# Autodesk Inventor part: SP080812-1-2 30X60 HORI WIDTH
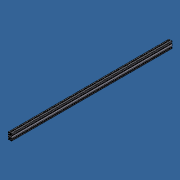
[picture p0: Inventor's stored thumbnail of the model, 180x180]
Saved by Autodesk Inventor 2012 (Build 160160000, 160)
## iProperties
Created: 2012-08
Part Number: SP080812-1-2 30X60 HORI WIDTH
Material: Aluminum-6061
Description: PROFILE 30X60
Document SubType Name: Modeling
Designer: Administrator
Stock Number: 20.0994 PROFILE 30X60
Density: 2.71 g/cm^3
Author: Administrator
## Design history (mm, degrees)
sketch "Sketch1"
  geometry: L1 (-12.5, -19.1)-(-12.5, -21.8); L2 (-15, -19.1)-(-12.5, -19.1); L3 (-15, -30)-(-15, -19.1); L4 (-4.1, -30)-(-15, -30); L5 (-4.1, -27.5)-(-4.1, -30); L6 (-6.8, -27.5)-(-4.1, -27.5); L7 (-6.8, -22.861)-(-6.8, -27.5); L8 (-3.939, -20)-(-6.8, -22.861); L9 (3.939, -20)-(-3.939, -20); L10 (6.8, -22.861)-(3.939, -20); L11 (6.8, -27.5)-(6.8, -22.861); L12 (4.1, -27.5)-(6.8, -27.5); L13 (4.1, -30)-(4.1, -27.5); L14 (15, -30)-(4.1, -30); L15 (15, -19.1)-(15, -30); L16 (12.5, -19.1)-(15, -19.1); L17 (12.5, -21.8)-(12.5, -19.1); L18 (7.861, -21.8)-(12.5, -21.8); L19 (5, -18.939)-(7.861, -21.8); L20 (5, -11.061)-(5, -18.939); L21 (7.861, -8.2)-(5, -11.061); L22 (12.5, -8.2)-(7.861, -8.2); L23 (12.5, -10.9)-(12.5, -8.2); L24 (15, -10.9)-(12.5, -10.9); L25 (15, 10.9)-(15, -10.9); L26 (12.5, 10.9)-(15, 10.9); L27 (12.5, 8.2)-(12.5, 10.9); L28 (7.861, 8.2)-(12.5, 8.2); L29 (5, 11.061)-(7.861, 8.2); L30 (5, 18.939)-(5, 11.061); L31 (7.861, 21.8)-(5, 18.939); L32 (12.5, 21.8)-(7.861, 21.8); L33 (12.5, 19.1)-(12.5, 21.8); L34 (15, 19.1)-(12.5, 19.1); L35 (15, 30)-(15, 19.1); L36 (4.1, 30)-(15, 30); L37 (4.1, 27.5)-(4.1, 30); L38 (6.8, 27.5)-(4.1, 27.5); L39 (6.8, 22.861)-(6.8, 27.5); L40 (3.939, 20)-(6.8, 22.861); L41 (-3.939, 20)-(3.939, 20); L42 (-6.8, 22.861)-(-3.939, 20); L43 (-6.8, 27.5)-(-6.8, 22.861); L44 (-4.1, 27.5)-(-6.8, 27.5); L45 (-4.1, 30)-(-4.1, 27.5); L46 (-15, 30)-(-4.1, 30); L47 (-15, 19.1)-(-15, 30); L48 (-12.5, 19.1)-(-15, 19.1); L49 (-12.5, 21.8)-(-12.5, 19.1); L50 (-7.861, 21.8)-(-12.5, 21.8); L51 (-5, 18.939)-(-7.861, 21.8); L52 (-5, 11.061)-(-5, 18.939); L53 (-7.861, 8.2)-(-5, 11.061); L54 (-12.5, 8.2)-(-7.861, 8.2); L55 (-12.5, 10.9)-(-12.5, 8.2); L56 (-15, 10.9)-(-12.5, 10.9); L57 (-15, -10.9)-(-15, 10.9); L58 (-12.5, -10.9)-(-15, -10.9); L59 (-12.5, -8.2)-(-12.5, -10.9); L60 (-7.861, -8.2)-(-12.5, -8.2); L61 (-5, -11.061)-(-7.861, -8.2); L62 (-5, -18.939)-(-5, -11.061); L63 (-7.861, -21.8)-(-5, -18.939); L64 (-12.5, -21.8)-(-7.861, -21.8)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; A1 r 0.5 centre (13.5, -23.3) between (14, -23.3) and (13.5, -22.8); A2 r 1.5 centre (12.5, -27.5) between (12.5, -29) and (14, -27.5); A3 r 0.5 centre (8.3, -28.5) between (7.8, -28.5) and (8.3, -29); A4 r 1.5 centre (9.3, -24.3) between (9.3, -22.8) and (7.8, -24.3); A5 r 0.5 centre (-8.3, -28.5) between (-8.3, -29) and (-7.8, -28.5); A6 r 1.5 centre (-12.5, -27.5) between (-14, -27.5) and (-12.5, -29); A7 r 0.5 centre (-13.5, -23.3) between (-13.5, -22.8) and (-14, -23.3); A8 r 1.5 centre (-9.3, -24.3) between (-7.8, -24.3) and (-9.3, -22.8); A9 r 0.3 centre (-1.793, -11.369) between (-2.005, -11.581) and (-1.66, -11.638); A10 r 3.75 centre (0, -15) between (1.66, -11.638) and (-1.66, -11.638); A11 r 0.3 centre (1.793, -11.369) between (1.66, -11.638) and (2.005, -11.581); A12 r 0.5 centre (3, -12) between (3.5, -12) and (3, -11.5); A13 r 0.3 centre (3.631, -13.207) between (3.419, -12.995) and (3.362, -13.34); A14 r 3.75 centre (0, -15) between (3.362, -16.66) and (3.362, -13.34); A15 r 0.3 centre (3.631, -16.793) between (3.362, -16.66) and (3.419, -17.005); A16 r 0.5 centre (3, -18) between (3, -18.5) and (3.5, -18); A17 r 0.3 centre (1.793, -18.631) between (2.005, -18.419) and (1.66, -18.362); A18 r 3.75 centre (0, -15) between (-1.66, -18.362) and (1.66, -18.362); A19 r 0.3 centre (-1.793, -18.631) between (-1.66, -18.362) and (-2.005, -18.419); A20 r 0.5 centre (-3, -18) between (-3.5, -18) and (-3, -18.5); A21 r 0.3 centre (-3.631, -16.793) between (-3.419, -17.005) and (-3.362, -16.66); A22 r 3.75 centre (0, -15) between (-3.362, -13.34) and (-3.362, -16.66); A23 r 0.3 centre (-3.631, -13.207) between (-3.362, -13.34) and (-3.419, -12.995); A24 r 0.5 centre (-3, -12) between (-3, -11.5) and (-3.5, -12); A25 r 0.5 centre (13.5, 6.7) between (14, 6.7) and (13.5, 7.2); A26 r 0.5 centre (13.5, -6.7) between (13.5, -7.2) and (14, -6.7); A27 r 1 centre (7.154, -8.2) between (7.154, -7.2) and (6.446, -7.493); A28 r 1 centre (3.525, -9) between (3.525, -10) and (4.232, -9.707); A29 r 1 centre (-3.525, -9) between (-4.232, -9.707) and (-3.525, -10); A30 r 1 centre (-7.154, -8.2) between (-6.446, -7.493) and (-7.154, -7.2); A31 r 0.5 centre (-13.5, -6.7) between (-14, -6.7) and (-13.5, -7.2); A32 r 0.5 centre (-13.5, 6.7) between (-13.5, 7.2) and (-14, 6.7); A33 r 1 centre (-7.154, 8.2) between (-7.154, 7.2) and (-6.446, 7.493); A34 r 1 centre (-3.525, 9) between (-3.525, 10) and (-4.232, 9.707); A35 r 1 centre (3.525, 9) between (4.232, 9.707) and (3.525, 10); A36 r 1 centre (7.154, 8.2) between (6.446, 7.493) and (7.154, 7.2); A37 r 0.3 centre (3.631, 16.793) between (3.419, 17.005) and (3.362, 16.66); A38 r 3.75 centre (0, 15) between (3.362, 13.34) and (3.362, 16.66); A39 r 0.3 centre (3.631, 13.207) between (3.362, 13.34) and (3.419, 12.995); A40 r 0.5 centre (3, 12) between (3, 11.5) and (3.5, 12); A41 r 0.3 centre (1.793, 11.369) between (2.005, 11.581) and (1.66, 11.638); A42 r 3.75 centre (0, 15) between (-1.66, 11.638) and (1.66, 11.638); A43 r 0.3 centre (-1.793, 11.369) between (-1.66, 11.638) and (-2.005, 11.581); A44 r 0.5 centre (-3, 12) between (-3.5, 12) and (-3, 11.5); A45 r 0.3 centre (-3.631, 13.207) between (-3.419, 12.995) and (-3.362, 13.34); A46 r 3.75 centre (0, 15) between (-3.362, 16.66) and (-3.362, 13.34); A47 r 0.3 centre (-3.631, 16.793) between (-3.362, 16.66) and (-3.419, 17.005); A48 r 0.5 centre (-3, 18) between (-3, 18.5) and (-3.5, 18); A49 r 0.3 centre (-1.793, 18.631) between (-2.005, 18.419) and (-1.66, 18.362); A50 r 3.75 centre (0, 15) between (1.66, 18.362) and (-1.66, 18.362); A51 r 0.3 centre (1.793, 18.631) between (1.66, 18.362) and (2.005, 18.419); A52 r 0.5 centre (3, 18) between (3.5, 18) and (3, 18.5); A53 r 0.5 centre (-8.3, 28.5) between (-7.8, 28.5) and (-8.3, 29); A54 r 1.5 centre (-9.3, 24.3) between (-9.3, 22.8) and (-7.8, 24.3); A55 r 0.5 centre (-13.5, 23.3) between (-14, 23.3) and (-13.5, 22.8); A56 r 1.5 centre (-12.5, 27.5) between (-12.5, 29) and (-14, 27.5); A57 r 0.5 centre (13.5, 23.3) between (13.5, 22.8) and (14, 23.3); A58 r 1.5 centre (9.3, 24.3) between (7.8, 24.3) and (9.3, 22.8); A59 r 0.5 centre (8.3, 28.5) between (8.3, 29) and (7.8, 28.5); A60 r 1.5 centre (12.5, 27.5) between (14, 27.5) and (12.5, 29); 1 further point
  constraints: 248 end point, 120 point on circle, 60 centre point
extrude "Extrusion1" new body sketch "Sketch1" stored distance "d3" = 1464; taper "d4" = 0 deg
body "Solid1"
